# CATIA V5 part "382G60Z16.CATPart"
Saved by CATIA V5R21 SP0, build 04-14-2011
Part number: 382G60Z16
Bounding box of the stored display mesh (mm): x -131.403 to 131.403, y -131.403 to 131.403, z -20 to 20
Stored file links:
  C:\Users\ALI OZGUN\Desktop\alhan\382G60Z16.CATPart
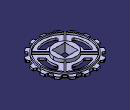
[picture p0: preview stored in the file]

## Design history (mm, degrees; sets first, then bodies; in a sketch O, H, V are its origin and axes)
Body1 (main body)
  Sketch1 on xy-plane, origin (0, 0, 0), H (1, 0, 0), V (0, 1, 0)
    circle A1 centre (0, 0) radius 132.5
    radius A1 = 132.5
  Pad1: profile Sketch1, direction (0, 0, 1), length 4.85, mirrored extent
  Sketch2 on end face of Pad1, origin (0, 0, 4.85), H (1, 0, 0), V (0, 1, 0)
    line L1 (-15.0612, 130.2617) -> (-10.5897, 120.8269)
    arc A1 centre (0, 0) radius 120 from (8.6385, 119.6887) to (-8.6385, 119.6887) ccw
    projected circle E1 centre (0, 0) radius 132.5 from edge [face of Pad1 from Sketch1.A1 | end face of Pad1]
    projected arc E2 centre (0, 0) radius 132.5 from (-17.127, 131.3884) to (-25.5392, 130.0154) ccw from edge [face of Pad1 from Sketch1.A1 | end face of Pad1]
    point P1 (-15.5, 131.1877)
    point P2 (-10, 119.5826)
    line L2 (15.0612, 130.2617) -> (10.5897, 120.8269)
    arc A2 centre (-8.7824, 121.6835) radius 2 from (-10.5897, 120.8269) to (-8.6385, 119.6887) ccw
    arc A3 centre (8.7824, 121.6835) radius 2 from (8.6385, 119.6887) to (10.5897, 120.8269) ccw
    line L3 (-31.529, 142.6538) -> (-25.5392, 130.0154)
    point P9 (-24.1515, 127.0874)
    point P10 (-19.2413, 116.7267)
    construction line L4 (-15.5, 131.1877) -> (-24.1515, 127.0874)
    construction line L5 (-10.5897, 120.8269) -> (-19.2413, 116.7267)
    offset circle E3 centre (0, 0) radius 146.0965 from edge [face of Pad1 from Sketch1.A1 | end face of Pad1]
    offset arc E4 centre (0, 0) radius 146.0965 from (31.529, 142.6538) to (-31.529, 142.6538) ccw from edge [face of Pad1 from Sketch1.A1 | end face of Pad1]
    line L6 (31.529, 142.6538) -> (25.5392, 130.0154)
    construction circle A4 centre (0, 0) radius 132.5
    arc A5 centre (0, 0) radius 132.5 from (17.127, 131.3884) to (25.5392, 130.0154) cw
    arc A6 centre (-16.8685, 129.4052) radius 2 from (-15.0612, 130.2617) to (-17.127, 131.3884) ccw
    arc A7 centre (16.8685, 129.4052) radius 2 from (17.127, 131.3884) to (15.0612, 130.2617) ccw
    distance P1 V = 15.5
    distance P2 V = 10
    radius A2 = 2
    radius A3 = 2 {= Sketch2.radius(A2)}
    distance L1 L3 = 9.574
    radius A6 = 2
    radius A7 = 2 {= Sketch2.radius(A6)}
    radius A1 = 120
    symmetry: L1 L2 V, E1 A4 V, L3 L6 V, E1 A5 V
    coincidence: L1 P2, A1 P2, P9 L3, P10 L3, P1 L1
    tangency: A2 L1, A2 A1, A3 A1, A3 L2, A6 L1, A6 E1, A7 A5, A7 L2
    perpendicularity: L4 L1, L4 L3, L5 L1, L5 L3
  Pocket1: profile Sketch2, direction (0, 0, -1), through (limit type 6)
  CircPattern1: of Pocket1, instances 16, angular step 22.5, axis from face of Pad1 from Sketch1.A1
  Sketch3 on xy-plane, origin (0, 0, 0), H (1, 0, 0), V (0, 1, 0)
    circle A1 centre (0, 0) radius 112
    radius A1 = 112
  Pad2: profile Sketch3, direction (0, 0, 1), length 13, mirrored extent, thin wall 5.5
  Sketch4 on xy-plane, origin (0, 0, 0), H (1, 0, 0), V (0, 1, 0)
    circle A1 centre (0, 0) radius 51.25
    radius A1 = 51.25
  Pad3: profile Sketch4, direction (0, 0, 1), length 20, mirrored extent
  Sketch5 on xy-plane, origin (0, 0, 0), H (1, 0, 0), V (0, 1, 0)
    line L1 (30, 30) -> (30, -30)
    line L2 (30, -30) -> (-30, -30)
    line L3 (-30, -30) -> (-30, 30)
    line L4 (-30, 30) -> (30, 30)
    length L1 = 60
    length L4 = 60
    vertical: L1 V, L3 V
    horizontal: L2 H, L4 H
    equidistance: L1 L3 O, L2 L4 O
  Pocket2: profile Sketch5, direction (0, 0, -1), length 21, mirrored extent
  Sketch6 on xy-plane, origin (0, 0, 0), H (1, 0, 0), V (0, 1, 0)
    line L1 (-77.2514, 77.2514) -> (-36.2392, 36.2392)
    point P1 (-77.2514, 77.2514)
    point P2 (77.2514, -77.2514)
    line L2 (77.2514, 77.2514) -> (36.2392, 36.2392)
    point P3 (77.2514, 77.2514)
    point P4 (-77.2514, -77.2514)
    reference projected circle E1 centre (0, 0) radius 109.25 from edge [end face of Pad2 | face of Pad2]
    reference projected circle E2 centre (0, 0) radius 51.25 from edge [face of Pad3 from Sketch4.A1 | end face of Pad3]
    point P5 (36.2392, 36.2392)
    line L3 (-36.2392, -36.2392) -> (-77.2514, -77.2514)
    point P6 (-36.2392, 36.2392)
    line L4 (36.2392, -36.2392) -> (77.2514, -77.2514)
    point P7 (-36.2392, -36.2392)
    point P8 (36.2392, -36.2392)
    angle L2 L1 = 90
    angle L1 V = 45
    coincidence: L1 O, L2 O, P1 E1, P3 E1, P2 E1, P4 E1, E2 P5, L2 L3, E2 P6, L1 L4, E2 P7, E2 P8
  Pad4: profile Sketch6, direction (0, 0, 1), length 13, mirrored extent, thin wall 6
  Sketch7 on xy-plane, origin (0, 0, 0), H (1, 0, 0), V (0, 1, 0)
    offset line E5 (60.9588, 93.4857) -> (19.9758, 52.5027) from edge [face of Pad4 | face of Pad4]
    offset line E6 (44.0319, 76.5588) -> (30.0645, 62.5914) from edge [face of Pad4 | face of Pad4]
    offset arc E7 centre (0, 0) radius 94.75 from (65.1333, 68.8129) to (-65.1333, 68.8129) ccw from edge [face of Pad4 | face of Pad2]
    offset arc E8 centre (0, 0) radius 94.75 from (42.7524, 84.5564) to (-42.7524, 84.5564) ccw from edge [face of Pad4 | face of Pad2]
    offset line E9 (-60.9588, 93.4857) -> (-19.9758, 52.5027) from edge [face of Pad4 | face of Pad4]
    offset line E10 (-44.0319, 76.5588) -> (-30.0645, 62.5914) from edge [face of Pad4 | face of Pad4]
    offset circle E11 centre (0, 0) radius 66.25 from edge [face of Pad3 from Sketch4.A1 | end face of Pad3]
    offset arc E12 centre (0, 0) radius 66.25 from (24.6673, 61.4865) to (-24.6673, 61.4865) ccw from edge [face of Pad3 from Sketch4.A1 | end face of Pad3]
    arc A1 centre (-40.4964, 80.0944) radius 5 from (-42.7524, 84.5564) to (-44.0319, 76.5588) ccw
    arc A2 centre (-26.529, 66.127) radius 5 from (-24.6673, 61.4865) to (-30.0645, 62.5914) cw
    arc A3 centre (26.529, 66.127) radius 5 from (30.0645, 62.5914) to (24.6673, 61.4865) cw
    arc A4 centre (40.4964, 80.0944) radius 5 from (42.7524, 84.5564) to (44.0319, 76.5588) cw
    radius A1 = 5
    radius A2 = 5 {= Sketch7.radius(A1)}
    radius A3 = 5 {= Sketch7.radius(A1)}
    radius A4 = 5 {= Sketch7.radius(A1)}
    tangency: A1 E7, A1 E9, A2 E11, A2 E9, A3 E5, A3 E11, A4 E7, A4 E5
  Pocket3: profile Sketch7, direction (0, 0, -1), length 13, mirrored extent
  CircPattern2: of Pocket3, instances 4, angular step 90, axis from face of Pad2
